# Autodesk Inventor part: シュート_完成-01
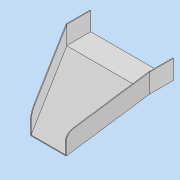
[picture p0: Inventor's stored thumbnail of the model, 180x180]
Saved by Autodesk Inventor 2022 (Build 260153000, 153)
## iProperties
Created: 2021-07
Part Number: シュート_完成-01
Material: 一般
Document SubType Name: Modeling
Designer: DesignLab
Density: 1 g/cm^3
Appearance: 既定
Author: DesignLab
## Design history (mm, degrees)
sketch "スケッチ1"
  geometry: L1 (-175, 0)-(175, 0); L2 (175, 0)-(175, 80); L3 (175, 80)-(-175, 80); L4 (-175, 80)-(-175, 0); 2 further points
  constraints: 8 end point, 2 parallel, 1 coincident, 1 horizontal, 1 midpoint, 1 perpendicular
  dimensions: "コンベア側幅" = 350 distance of L3.end L2.end; "d1" = 80 distance of L2.end L1.end
extrude "押し出し1" new body sketch "スケッチ1" distance "d2" = 100; taper "d3" = 0 deg
sketch "スケッチ2"
  geometry: L1 (0, 100)-(80, 100) reference; L2 (0, 100)-(-150, 350); 1 further point
  constraints: 2 end point
  dimensions: "シュート高さ" = 150 horizontal distance of L1.start L2.end; "シュート長さ" = 250 vertical distance of L1.start L2.end
node "作業平面1"
sketch "スケッチ3"
  geometry: L1 (-75, 0)-(75, 0); L2 (75, 0)-(75, 80); L3 (75, 80)-(-75, 80); L4 (-75, 80)-(-75, 0); 3 further points
  constraints: 8 end point, 2 parallel, 1 coincident, 1 horizontal, 1 midpoint, 1 perpendicular
  dimensions: "d6" = 150 distance of L3.end L2.end; "d7" = 80 distance of L2.end L1.end
feature "ロフト1" sketch "スケッチ3" dims "d8" = 0, "d9" = 90 deg, "d10" = 0, "d11" = 90 deg
  node "エッジ1"
fillet "フィレット1" dims "d12" = 50
feature "シェル1" dims "d13" = 3
node "ソリッド1"
